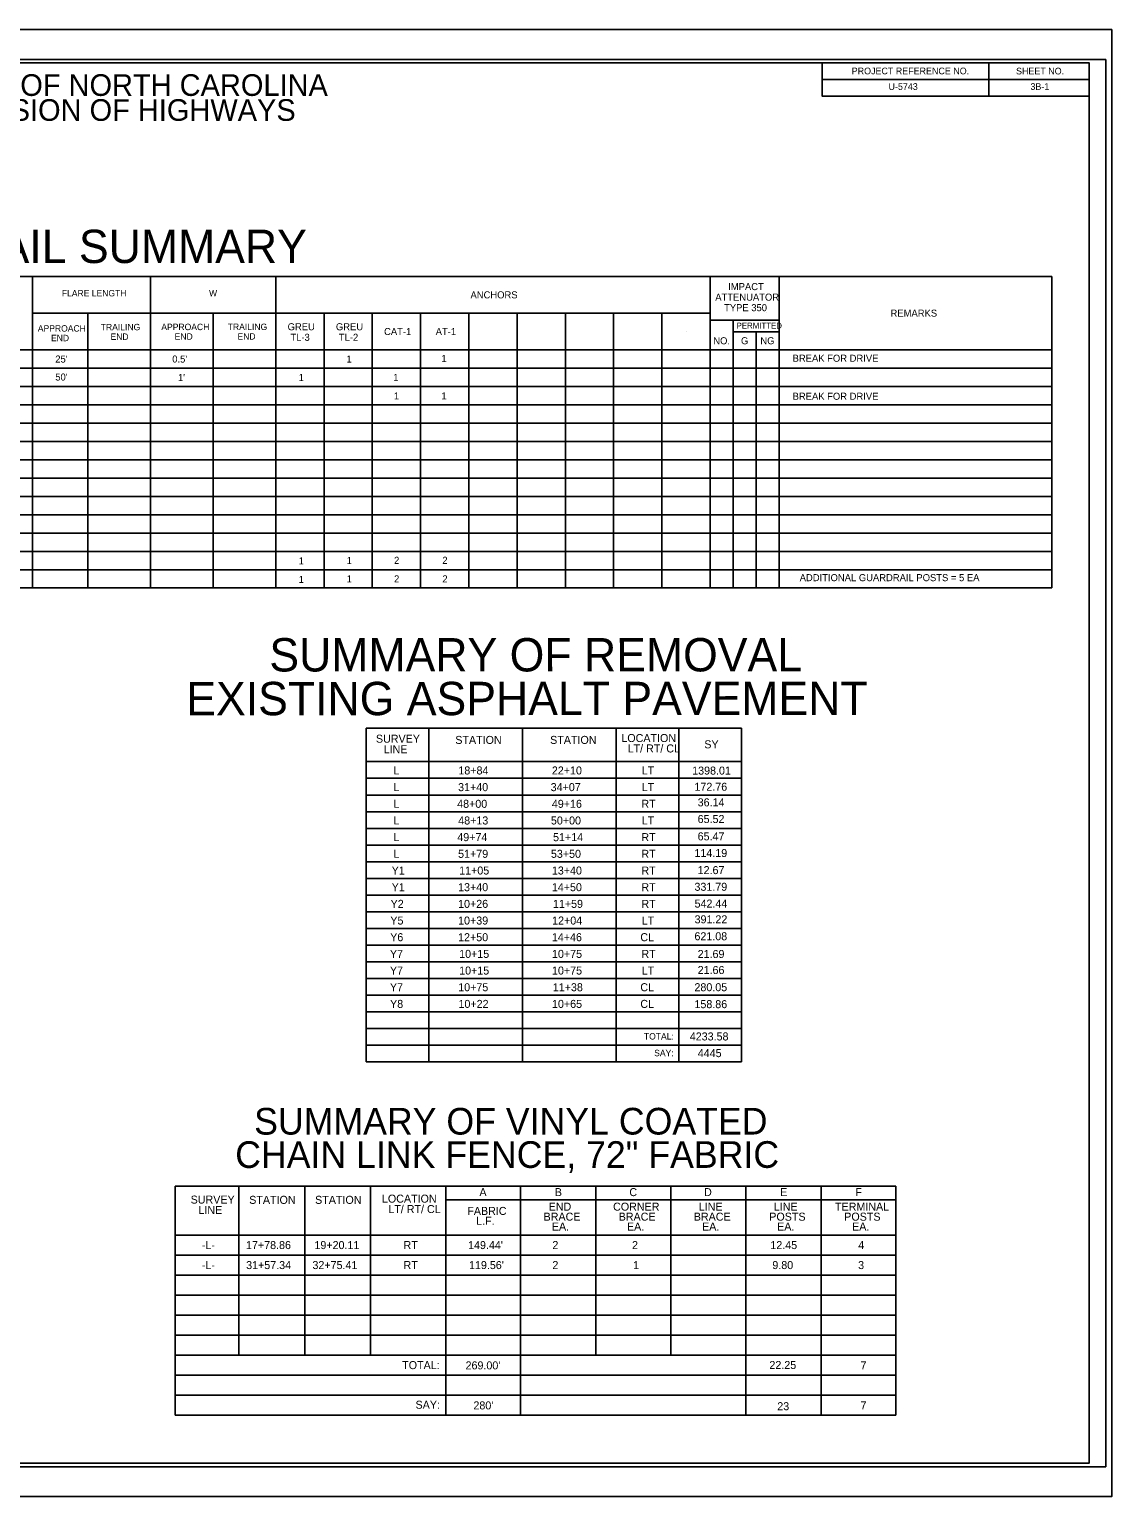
# Model space of a CAD drawing. Extents: x 1852861 to 1855026, y 258638 to 259806.
# Drawn here: x 1853734 to 1854545, y 258638 to 259738 of the extents above; entities that cross this region are included whole.
import ezdxf

# ---------------------------------------------------------------- set-up
doc = ezdxf.new("R2010")
doc.units = 0
for name, color, linetype in [('Old_Level_44', 7, 'Continuous'), ('Sheet Cutting Line CELL', 7, 'Continuous'), ('Sheet Pipe Summary Grid CELL', 7, 'Continuous'), ('Sheet Plot Border Inside CELL', 7, 'Continuous'), ('Sheet Plot Border Outside CELL', 7, 'Continuous'), ('Sheet Summary Combination CELL', 7, 'Continuous'), ('Sheet Summary Combination Grid CELL', 7, 'Continuous'), ('Sheet Summary Guardrail CELL', 7, 'Continuous')]:
    doc.layers.add(name, color=color, linetype=linetype)

msp = doc.modelspace()

# ---------------------------------------------------------------- linework, layer by layer
at = {"layer": 'Sheet Cutting Line CELL'}
for p, q in [((1854545.1, 259738.5), (1852861.1, 259738.5)), ((1852861.1, 258638.5), (1854545.1, 258638.5))]:
    msp.add_line(p, q, dxfattribs=at)
at = {"layer": 'Sheet Pipe Summary Grid CELL'}
for p, q in [((1853843, 258871.3), (1854180.6, 258871.3)), ((1853843, 258871.3), (1853843, 258699.6)), ((1853890.7, 258871.3), (1853890.7, 258744.6)), ((1853940.1, 258871.3), (1853940.1, 258744.6)), ((1853989.5, 258871.3), (1853989.5, 258744.6)), ((1854045.8, 258871.3), (1854045.8, 258699.6)), ((1854102, 258871.3), (1854102, 258699.6)), ((1854158.3, 258871.3), (1854158.3, 258744.6)), ((1854180.6, 258871.3), (1854383.4, 258871.3)), ((1854214.6, 258871.3), (1854214.6, 258744.6)), ((1854270.9, 258871.3), (1854270.9, 258699.6)), ((1854327.2, 258871.3), (1854327.2, 258699.6)), ((1854383.4, 258871.3), (1854383.4, 258699.6)), ((1854045.6, 258861), (1854383.2, 258861)), ((1853843, 258834.6), (1854180.6, 258834.6)), ((1854180.6, 258834.6), (1854383.4, 258834.6)), ((1853843, 258819.6), (1854180.6, 258819.6)), ((1854180.6, 258819.6), (1854383.4, 258819.6)), ((1853843, 258804.6), (1854180.6, 258804.6)), ((1854180.6, 258804.6), (1854383.4, 258804.6)), ((1853843, 258789.6), (1854180.6, 258789.6)), ((1854180.6, 258789.6), (1854383.4, 258789.6)), ((1853843, 258774.6), (1854180.6, 258774.6)), ((1854180.6, 258774.6), (1854383.4, 258774.6)), ((1853843, 258759.6), (1854180.6, 258759.6)), ((1854180.6, 258759.6), (1854383.4, 258759.6)), ((1853843, 258744.6), (1854180.6, 258744.6)), ((1854180.6, 258744.6), (1854383.4, 258744.6)), ((1853843, 258729.6), (1854180.6, 258729.6)), ((1854180.6, 258729.6), (1854383.4, 258729.6)), ((1853843, 258714.6), (1854180.6, 258714.6)), ((1854180.6, 258714.6), (1854383.4, 258714.6)), ((1853843, 258699.6), (1854180.6, 258699.6)), ((1854180.6, 258699.6), (1854383.4, 258699.6))]:
    msp.add_line(p, q, dxfattribs=at)
at = {"layer": 'Sheet Plot Border Inside CELL'}
msp.add_lwpolyline([(1854540.6, 259716), (1852874.1, 259716), (1852874.1, 258660.9), (1854540.6, 258660.9)], close=True, dxfattribs=at)
at = {"layer": 'Sheet Plot Border Outside CELL'}
msp.add_lwpolyline([(1854545.1, 259738.5), (1852861.1, 259738.5), (1852861.1, 258638.5), (1854545.1, 258638.5)], close=True, dxfattribs=at)
at = {"layer": 'Sheet Summary Combination CELL'}
for p, q in [((1854453.1, 259713.4), (1854453.1, 259688.4)), ((1854328, 259700.9), (1854528.1, 259700.9)), ((1854328, 259688.4), (1854528.1, 259688.4)), ((1854127.4, 259214.4), (1854127.4, 259214.4)), ((1854133.7, 259214.3), (1854133.7, 259214.3)), ((1854142.7, 259214.5), (1854142.7, 259214.5)), ((1854148.3, 259214.4), (1854148.3, 259214.4))]:
    msp.add_line(p, q, dxfattribs=at)
for points in [[(1854528.1, 259713.5), (1853028.1, 259713.5), (1853028.1, 258663.5), (1854528.1, 258663.5)], [(1854328, 259713.5), (1854528.1, 259713.5), (1854528.1, 259688.4), (1854328, 259688.4)]]:
    msp.add_lwpolyline(points, close=True, dxfattribs=at)
at = {"layer": 'Sheet Summary Combination Grid CELL'}
for p, q in [((1853986.2, 259214.5), (1854267.5, 259214.5)), ((1853986.2, 259214.5), (1853986.2, 258964.5)), ((1854033.1, 259214.5), (1854033.1, 258964.5)), ((1854103.4, 259214.5), (1854103.4, 258964.5)), ((1854173.7, 259214.5), (1854173.7, 258964.5)), ((1854220.6, 259214.5), (1854220.6, 258964.5)), ((1854267.5, 259214.5), (1854267.5, 258964.5)), ((1853986.2, 259189.5), (1854267.5, 259189.5)), ((1853986.2, 259177), (1854267.5, 259177)), ((1853986.2, 259164.5), (1854267.5, 259164.5)), ((1853986.2, 259152), (1854267.5, 259152)), ((1853986.2, 259139.5), (1854267.5, 259139.5)), ((1853986.2, 259127), (1854267.5, 259127)), ((1853986.2, 259114.5), (1854267.5, 259114.5)), ((1853986.2, 259102), (1854267.5, 259102)), ((1853986.2, 259089.5), (1854267.5, 259089.5)), ((1853986.2, 259077), (1854267.5, 259077)), ((1853986.2, 259064.5), (1854267.5, 259064.5)), ((1853986.2, 259052), (1854267.5, 259052)), ((1853986.2, 259039.5), (1854267.5, 259039.5)), ((1853986.2, 259027), (1854267.5, 259027)), ((1853986.2, 259014.5), (1854267.5, 259014.5)), ((1853986.2, 259002), (1854267.5, 259002)), ((1853986.2, 258989.5), (1854267.5, 258989.5)), ((1853986.2, 258989.5), (1854267.5, 258989.5)), ((1853986.2, 258977), (1854267.5, 258977)), ((1853986.2, 258977), (1854267.5, 258977)), ((1853986.2, 258964.5), (1854267.5, 258964.5)), ((1853986.2, 258964.5), (1854267.5, 258964.5))]:
    msp.add_line(p, q, dxfattribs=at)
at = {"layer": 'Sheet Summary Guardrail CELL'}
for p, q in [((1853051.9, 259553.2), (1854500.3, 259553.2)), ((1853736.1, 259553.2), (1853736.1, 259319.9)), ((1853824.4, 259553.2), (1853824.4, 259319.9)), ((1853918.4, 259553.2), (1853918.4, 259319.9)), ((1854244.1, 259553.2), (1854244.1, 259319.9)), ((1854295.8, 259553.2), (1854295.8, 259319.9)), ((1854500.3, 259553.2), (1854500.3, 259319.9)), ((1854244.1, 259525.7), (1853736.1, 259525.7)), ((1853777.4, 259525.7), (1853777.4, 259319.9)), ((1853871.4, 259525.7), (1853871.4, 259319.9)), ((1853954.6, 259525.7), (1853954.6, 259319.9)), ((1853990.7, 259525.7), (1853990.7, 259319.9)), ((1854026.9, 259525.7), (1854026.9, 259319.9)), ((1854063.1, 259525.7), (1854063.1, 259319.9)), ((1854099.3, 259525.7), (1854099.3, 259319.9)), ((1854135.5, 259525.7), (1854135.5, 259319.9)), ((1854171.7, 259525.7), (1854171.7, 259319.9)), ((1854207.9, 259525.7), (1854207.9, 259319.9)), ((1854286, 259526), (1854286, 259526)), ((1854244.1, 259520.5), (1854295.8, 259520.5)), ((1854261.3, 259520.5), (1854261.3, 259319.9)), ((1853972.6, 259512), (1853972.6, 259512)), ((1854045, 259512), (1854045, 259512)), ((1854226, 259512), (1854226, 259512)), ((1854261.3, 259511.7), (1854295.8, 259511.7)), ((1854278.5, 259511.7), (1854278.5, 259319.9)), ((1853051.9, 259498.2), (1854500.3, 259498.2)), ((1853051.9, 259484.5), (1854500.3, 259484.5)), ((1853051.9, 259470.7), (1854500.3, 259470.7)), ((1853051.9, 259457), (1854500.3, 259457)), ((1853051.9, 259443.2), (1854500.3, 259443.2)), ((1853051.9, 259429.5), (1854500.3, 259429.5)), ((1853051.9, 259415.7), (1854500.3, 259415.7)), ((1853051.9, 259402), (1854500.3, 259402)), ((1853051.9, 259388.2), (1854500.3, 259388.2)), ((1853051.9, 259374.5), (1854500.3, 259374.5)), ((1853051.9, 259360.7), (1854500.3, 259360.7)), ((1853051.9, 259347), (1854500.3, 259347)), ((1853051.9, 259333.4), (1854500.3, 259333.4)), ((1853051.9, 259319.9), (1854500.3, 259319.9)), ((1854003.9, 258871.3), (1854003.9, 258871.3)), ((1854011.4, 258871.2), (1854011.4, 258871.2)), ((1854030.9, 258871.4), (1854030.9, 258871.4)), ((1854037.6, 258871.3), (1854037.6, 258871.3))]:
    msp.add_line(p, q, dxfattribs=at)

# ---------------------------------------------------------------- texts
at = {"layer": 'Old_Level_44'}
for s, height, p in [('U-5743', 5, (1854377.8, 259693.1)), ('3B-1', 5, (1854484.2, 259693.1)), ('1398.01', 6, (1854230.6, 259179.8)), ('172.76', 6, (1854232.3, 259167.7)), ('36.14', 6, (1854234.7, 259156)), ('65.52', 6, (1854234.7, 259143.5)), ('65.47', 6, (1854234.7, 259130.5)), ('114.19', 6, (1854232.3, 259118)), ('12.67', 6, (1854234.7, 259105.2)), ('331.79', 6, (1854232.3, 259092.7)), ('542.44', 6, (1854232.4, 259080.1)), ('391.22', 6, (1854232.4, 259068.3)), ('621.08', 6, (1854232.3, 259055.6)), ('21.69', 6, (1854234.7, 259042.3)), ('21.66', 6, (1854234.7, 259030.3)), ('280.05', 6, (1854232.3, 259017.4)), ('158.86', 6, (1854232.3, 259004.7)), ('4233.58', 6, (1854228.8, 258980.5)), ('4445', 6, (1854234.8, 258968))]:
    msp.add_text(s, height=height, dxfattribs=at).set_placement(p)
for s, p in [('L', (1854006.7, 259179.9)), ('18+84', (1854055.3, 259179.9)), ('22+10', (1854125.4, 259179.9)), ('LT', (1854192.8, 259179.9)), ('L', (1854006.7, 259167.4)), ('31+40', (1854055.1, 259167.4)), ('34+07', (1854124.5, 259167.4)), ('LT', (1854192.8, 259167.4)), ('L', (1854006.7, 259154.9)), ('48+00', (1854054.4, 259154.9)), ('49+16', (1854125.4, 259154.9)), ('RT', (1854192.5, 259154.9)), ('L', (1854006.7, 259142.4)), ('48+13', (1854055.2, 259142.4)), ('50+00', (1854124.7, 259142.4)), ('LT', (1854192.8, 259142.4)), ('L', (1854006.7, 259129.9)), ('49+74', (1854054.5, 259129.9)), ('51+14', (1854126.3, 259129.9)), ('RT', (1854192.5, 259129.9)), ('L', (1854006.7, 259117.4)), ('51+79', (1854055.1, 259117.4)), ('53+50', (1854124.7, 259117.4)), ('RT', (1854192.5, 259117.4)), ('Y1', (1854005.3, 259104.9)), ('11+05', (1854055.9, 259104.9)), ('13+40', (1854125.4, 259104.9)), ('RT', (1854192.5, 259104.9)), ('Y1', (1854005.3, 259092.4)), ('13+40', (1854055.1, 259092.4)), ('14+50', (1854125.4, 259092.4)), ('RT', (1854192.5, 259092.4)), ('Y2', (1854004.5, 259079.9)), ('10+26', (1854055.1, 259079.9)), ('11+59', (1854126.2, 259079.9)), ('RT', (1854192.5, 259079.9)), ('Y5', (1854004.3, 259067.4)), ('10+39', (1854055.1, 259067.4)), ('12+04', (1854125.6, 259067.4)), ('LT', (1854192.8, 259067.4)), ('Y6', (1854004.2, 259054.9)), ('12+50', (1854055.1, 259054.9)), ('14+46', (1854125.4, 259054.9)), ('CL', (1854191.7, 259054.9)), ('Y7', (1854004, 259042.4)), ('10+15', (1854055.9, 259042.4)), ('10+75', (1854125.5, 259042.4)), ('RT', (1854192.5, 259042.4)), ('Y7', (1854004, 259029.9)), ('10+15', (1854055.9, 259029.9)), ('10+75', (1854125.5, 259029.9)), ('LT', (1854192.8, 259029.9)), ('Y7', (1854004, 259017.4)), ('10+75', (1854055.2, 259017.4)), ('11+38', (1854126.1, 259017.4)), ('CL', (1854191.7, 259017.4)), ('Y8', (1854004.1, 259004.9)), ('10+22', (1854055.4, 259004.9)), ('10+65', (1854125.5, 259004.9)), ('CL', (1854191.7, 259004.9))]:
    msp.add_text(s, height=6, rotation=0, dxfattribs=at).set_placement(p)
at = {"layer": 'Sheet Summary Combination CELL'}
for s, height, p in [('STATE OF NORTH CAROLINA', 16.25, (1853650.8, 259688.6)), ('PROJECT REFERENCE NO.', 5, (1854350.2, 259704.8)), ('SHEET NO.', 5, (1854473.4, 259704.7)), ('DIVISION OF HIGHWAYS', 16.25, (1853677.4, 259669.9)), ('SURVEY', 6, (1853993.5, 259203.7)), ('STATION', 6, (1854053, 259202.8)), ('STATION', 6, (1854124.1, 259202.8)), ('LOCATION', 6, (1854177.5, 259204.2)), ('LINE', 6, (1853999.3, 259195.8)), ('LT/ RT/ CL', 6, (1854182.2, 259196.4)), ('TOTAL:', 4.8, (1854194.4, 258981.2)), ('SAY:', 4.8, (1854202.1, 258968.7))]:
    msp.add_text(s, height=height, dxfattribs=at).set_placement(p)
for s, p in [('SUMMARY OF REMOVAL ', (1853913.6, 259257.1)), ('EXISTING ASPHALT PAVEMENT', (1853851.3, 259224.3))]:
    msp.add_text(s, height=25, rotation=0.0119, dxfattribs=at).set_placement(p)
at = {"layer": 'Sheet Summary Combination Grid CELL'}
msp.add_text('SY', height=6, dxfattribs=at).set_placement((1854239.7, 259199.5))
at = {"layer": 'Sheet Summary Guardrail CELL'}
for s, height, p in [('GUARDRAIL SUMMARY', 25, (1853566.5, 259563.3)), ('IMPACT', 5.28, (1854257.6, 259543)), ('FLARE LENGTH', 4.8, (1853758, 259538.3)), ('W', 4.8, (1853868.4, 259538.3)), ('ANCHORS', 5.28, (1854064.4, 259536.8)), ('ATTENUATOR', 5.28, (1854247.9, 259535.1)), ('TYPE 350', 5.28, (1854254.5, 259527.2)), ('REMARKS', 5.28, (1854379.3, 259523.1)), ('APPROACH', 4.8, (1853740, 259511.9)), ('TRAILING', 4.8, (1853787.2, 259512.9)), ('APPROACH', 4.8, (1853832.6, 259513)), ('TRAILING', 4.8, (1853882.4, 259513.1)), ('GREU', 5.28, (1853927.3, 259512.9)), ('GREU', 5.28, (1853963.5, 259512.9)), ('CAT-1', 5.28, (1853999.6, 259509.3)), ('AT-1', 5.28, (1854038.3, 259509.3)), ('PERMITTED', 4.4, (1854263.9, 259514.2)), ('END', 4.8, (1853749.9, 259504.7)), ('END', 4.8, (1853794.5, 259505.7)), ('END', 4.8, (1853842.6, 259505.8)), ('END', 4.8, (1853889.7, 259505.9)), ('TL-3', 5.28, (1853929.4, 259505)), ('TL-2', 5.28, (1853965.7, 259505)), ('NO.', 5.28, (1854246.4, 259502.4)), ('G', 5.28, (1854267.2, 259502.4)), ('NG', 5.28, (1854281.7, 259502.4)), ("25'", 5.28, (1853753.1, 259488.7)), ("0.5'", 5.28, (1853840.8, 259488.7)), ('1', 5.28, (1853971.4, 259488.7)), ('1', 5.28, (1854042.6, 259489.1)), ('BREAK FOR DRIVE', 5.28, (1854305.9, 259489.3)), ("50'", 5.28, (1853753.1, 259475.2)), ("1'", 5.28, (1853845.1, 259474.8)), ('1', 5.28, (1853935.6, 259474.9)), ('1', 5.28, (1854006.5, 259474.9)), ('1', 5.28, (1854006.9, 259461)), ('1', 5.28, (1854042.6, 259461.1)), ('BREAK FOR DRIVE', 5.28, (1854305.9, 259460.8)), ('1', 5.28, (1853935.6, 259337.4)), ('1', 5.28, (1853971.6, 259337.7)), ('2', 5.28, (1854007.1, 259337.8)), ('2', 5.28, (1854043.3, 259337.8)), ('1', 5.28, (1853935.6, 259323.5)), ('1', 5.28, (1853971.6, 259323.9)), ('2', 5.28, (1854007.1, 259323.9)), ('2', 5.28, (1854043.3, 259323.9)), ('ADDITIONAL GUARDRAIL POSTS = 5 EA', 5.28, (1854311.2, 259324.8)), ('SURVEY', 6, (1853854.6, 258858.2)), ('STATION', 6, (1853898.5, 258858)), ('STATION', 6, (1853947.9, 258858)), ('LOCATION', 6, (1853998, 258858.9)), ('A', 6, (1854071.1, 258863.8)), ('B', 6, (1854127.6, 258863.8)), ('C', 6, (1854183.5, 258863.8)), ('D', 6, (1854239.5, 258863.8)), ('E', 6, (1854296.6, 258863.8)), ('F', 6, (1854352.9, 258863.8)), ('LINE', 6, (1853860.4, 258850.4)), ('LT/ RT/ CL', 6, (1854002.8, 258851.1)), ('FABRIC', 6, (1854062, 258849.7)), ('END', 6, (1854123, 258852.9)), ('CORNER ', 6, (1854171.3, 258852.9)), ('LINE ', 6, (1854235.5, 258852.9)), ('LINE ', 6, (1854291.8, 258852.9)), ('TERMINAL ', 6, (1854337.7, 258852.9)), ('L.F.', 6, (1854068.7, 258842.3)), ('BRACE', 6, (1854119.2, 258845.4)), ('EA.', 6, (1854125.4, 258838)), ('BRACE', 6, (1854175.5, 258845.4)), ('EA.', 6, (1854181.7, 258838)), ('BRACE ', 6, (1854231.8, 258845.4)), ('EA.', 6, (1854238, 258838)), ('POSTS', 6, (1854288.4, 258845.4)), ('EA.', 6, (1854294.3, 258838)), ('POSTS', 6, (1854344.6, 258845.4)), ('EA.', 6, (1854350.5, 258838)), ('-L-', 6, (1853863, 258824.1)), ('17+78.86', 6, (1853896.1, 258824.1)), ('19+20.11', 6, (1853947.4, 258824.1)), ('RT', 6, (1854014.2, 258824.1)), ("149.44'", 6, (1854062.6, 258824.1)), ('2', 6, (1854125.8, 258824.1)), ('2', 6, (1854185.5, 258824.1)), ('12.45', 6, (1854289.2, 258824.1)), ('4', 6, (1854355.1, 258824.1)), ('-L-', 6, (1853863, 258809.1)), ('31+57.34', 6, (1853896.2, 258809.1)), ('32+75.41', 6, (1853945.9, 258809.1)), ('RT', 6, (1854014.2, 258809.1)), ("119.56'", 6, (1854063.3, 258809.1)), ('2', 6, (1854125.8, 258809.1)), ('1', 6, (1854186.3, 258809.1)), ('9.80', 6, (1854290.7, 258809.1)), ('3', 6, (1854355, 258809.1)), ('TOTAL:', 6, (1854013.2, 258734.1)), ("269.00'", 6, (1854060.7, 258733.9)), ('22.25', 6, (1854288.5, 258734.2)), ('7', 6, (1854356.8, 258733.9)), ('SAY:', 6, (1854023.2, 258704.4)), ("280'", 6, (1854066.6, 258703.9)), ('23', 6, (1854294.4, 258703.3)), ('7', 6, (1854356.8, 258703.9))]:
    msp.add_text(s, height=height, dxfattribs=at).set_placement(p)
for s, p in [('SUMMARY OF VINYL COATED ', (1853902.2, 258909.9)), ('CHAIN LINK FENCE, 72" FABRIC', (1853888, 258884.9))]:
    msp.add_text(s, height=20, rotation=0.0119, dxfattribs=at).set_placement(p)

doc.saveas('drawing.dxf')
